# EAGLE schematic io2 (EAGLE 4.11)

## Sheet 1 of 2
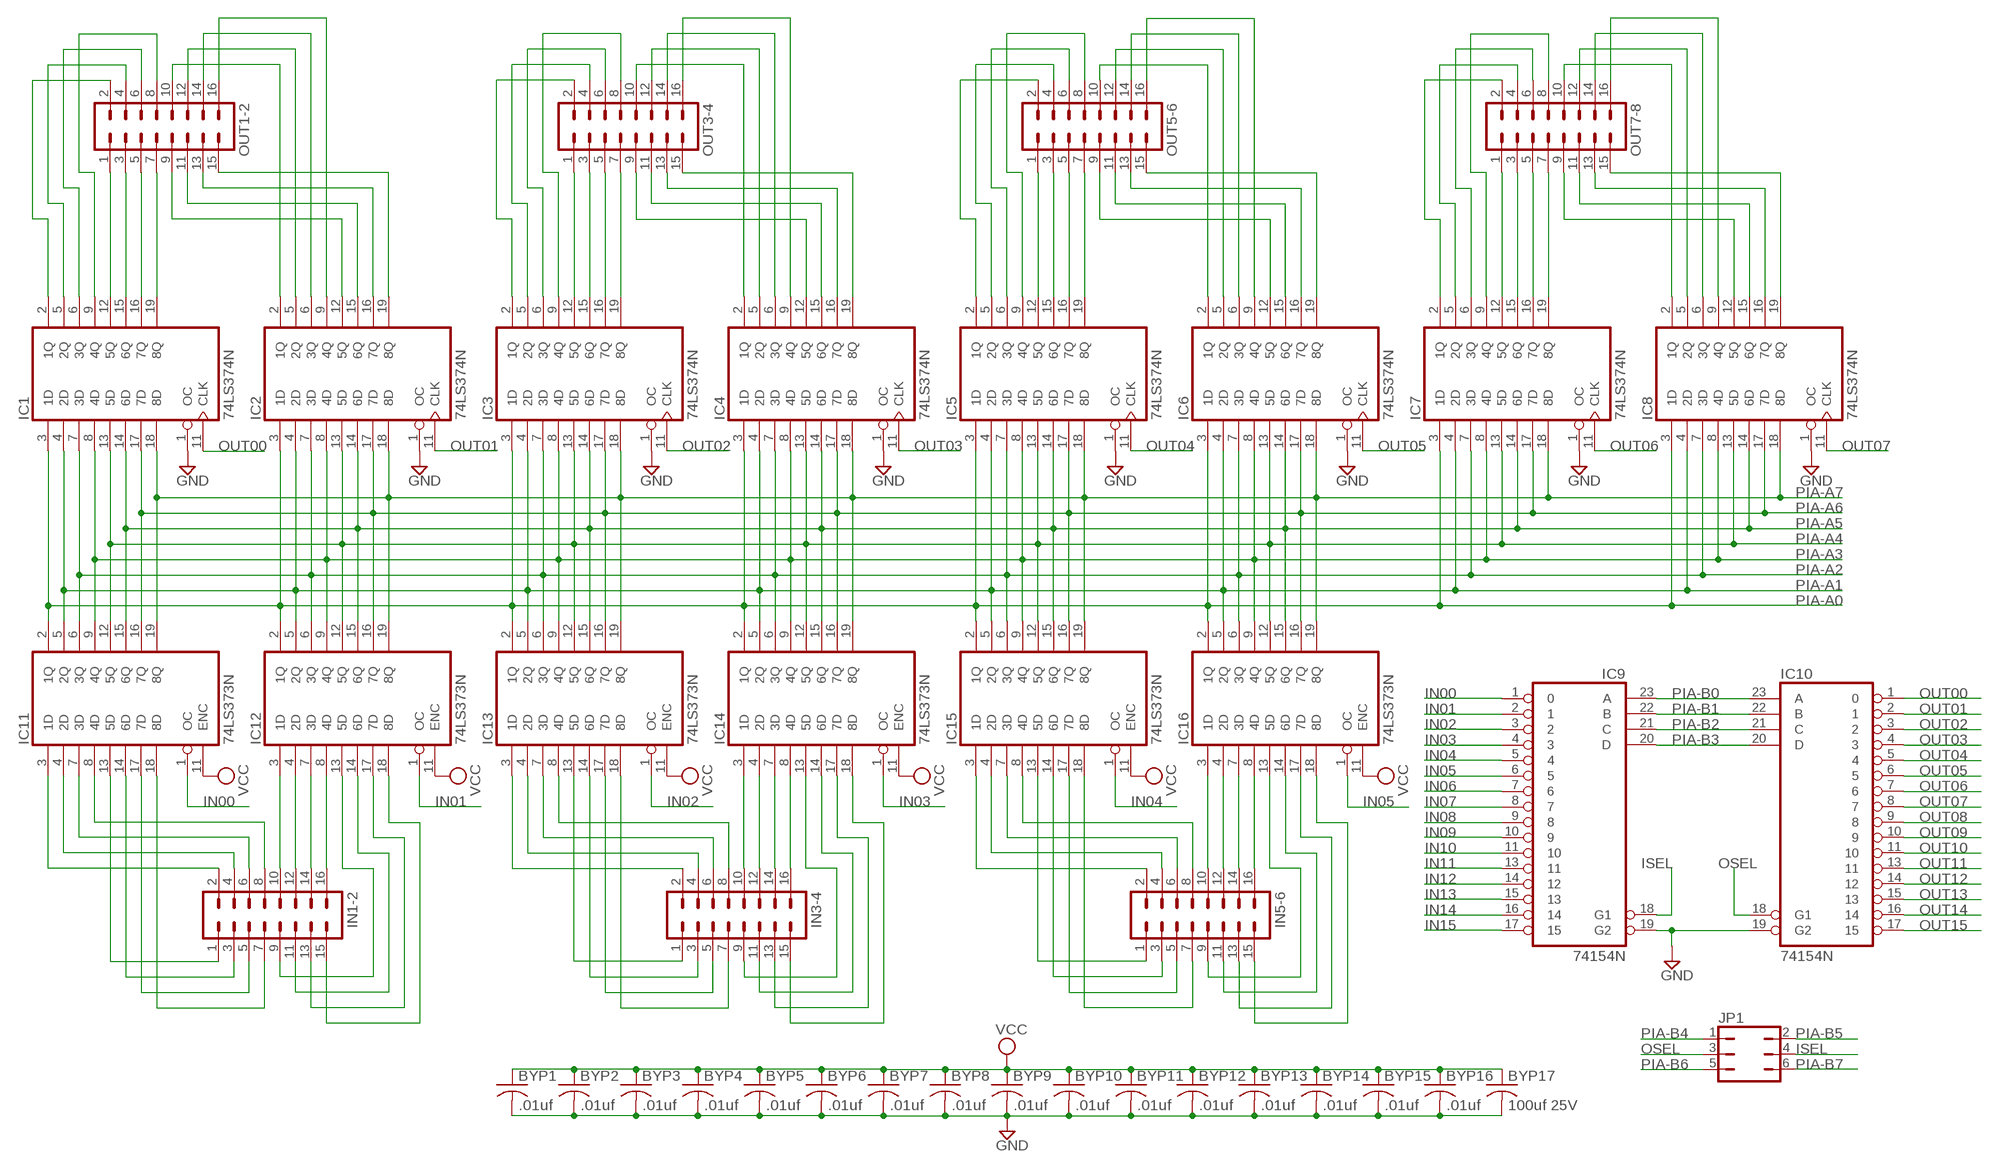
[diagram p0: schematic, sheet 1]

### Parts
BYP1  .01uf  C-US050-025X075  [C050-025X075]
BYP2  .01uf  C-US050-025X075  [C050-025X075]
BYP3  .01uf  C-US050-025X075  [C050-025X075]
BYP4  .01uf  C-US050-025X075  [C050-025X075]
BYP5  .01uf  C-US050-025X075  [C050-025X075]
BYP6  .01uf  C-US050-025X075  [C050-025X075]
BYP7  .01uf  C-US050-025X075  [C050-025X075]
BYP8  .01uf  C-US050-025X075  [C050-025X075]
BYP9  .01uf  C-US050-025X075  [C050-025X075]
BYP10  .01uf  C-US050-025X075  [C050-025X075]
BYP11  .01uf  C-US050-025X075  [C050-025X075]
BYP12  .01uf  C-US050-025X075  [C050-025X075]
BYP13  .01uf  C-US050-025X075  [C050-025X075]
BYP14  .01uf  C-US050-025X075  [C050-025X075]
BYP15  .01uf  C-US050-025X075  [C050-025X075]
BYP16  .01uf  C-US050-025X075  [C050-025X075]
BYP17  100uf 25V  C-US102-043X133  [C102-043X133]
IC1  74LS374N  [DIL20]
IC2  74LS374N  [DIL20]
IC3  74LS374N  [DIL20]
IC4  74LS374N  [DIL20]
IC5  74LS374N  [DIL20]
IC6  74LS374N  [DIL20]
IC7  74LS374N  [DIL20]
IC8  74LS374N  [DIL20]
IC9  74154N  [DIL24-6]
IC10  74154N  [DIL24-6]
IC11  74LS373N  [DIL20]
IC12  74LS373N  [DIL20]
IC13  74LS373N  [DIL20]
IC14  74LS373N  [DIL20]
IC15  74LS373N  [DIL20]
IC16  74LS373N  [DIL20]
IN1-2  MA08-2  [MA08-2]
IN3-4  MA08-2  [MA08-2]
IN5-6  MA08-2  [MA08-2]
JP1  JP3Q  [JP3Q]
OUT1-2  MA08-2  [MA08-2]
OUT3-4  MA08-2  [MA08-2]
OUT5-6  MA08-2  [MA08-2]
OUT7-8  MA08-2  [MA08-2]

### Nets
GND [Power]: BYP1.2 BYP2.2 BYP3.2 BYP4.2 BYP5.2 BYP6.2 BYP7.2 BYP8.2 BYP9.2 BYP10.2 BYP11.2 BYP12.2 BYP13.2 BYP14.2 BYP15.2 BYP16.2 BYP17.2 IC1.1(OC) IC2.1(OC) IC3.1(OC) IC4.1(OC) IC5.1(OC) IC6.1(OC) IC7.1(OC) IC8.1(OC) IC9.19(G2) IC10.19(G2) ; also sheet 2
IN00: IC9.1 IC11.1(OC)
IN01: IC9.2 IC12.1(OC)
IN02: IC9.3 IC13.1(OC)
IN03: IC9.4 IC14.1(OC)
IN04: IC9.5 IC15.1(OC)
IN05: IC9.6 IC16.1(OC)
IN06: IC9.7
IN07: IC9.8
IN08: IC9.9
IN09: IC9.10
IN10: IC9.11
IN11: IC9.13
IN12: IC9.14
IN13: IC9.15
IN14: IC9.16
IN15: IC9.17
ISEL: IC9.18(G1) JP1.4
N$1: IC12.3(1D) IN1-2.10
N$2: IC12.4(2D) IN1-2.12
N$7: IC12.7(3D) IN1-2.14
N$8: IC12.8(4D) IN1-2.16
N$9: IC11.8(4D) IN1-2.8
N$10: IC11.7(3D) IN1-2.6
N$11: IC11.4(2D) IN1-2.4
N$12: IC11.3(1D) IN1-2.2
N$13: IC11.13(5D) IN1-2.1
N$14: IC11.14(6D) IN1-2.3
N$15: IC11.17(7D) IN1-2.5
N$16: IC11.18(8D) IN1-2.7
N$17: IC12.13(5D) IN1-2.9
N$18: IC12.14(6D) IN1-2.11
N$19: IC12.17(7D) IN1-2.13
N$20: IC12.18(8D) IN1-2.15
N$26: IC5.2(1Q) IC7.2(1Q) OUT5-6.2 OUT7-8.2
N$29: IC14.3(1D) IN3-4.10
N$30: IC14.4(2D) IN3-4.12
N$31: IC14.7(3D) IN3-4.14
N$32: IC14.8(4D) IN3-4.16
N$33: IC3.12(5Q) OUT3-4.1
N$34: IC3.15(6Q) OUT3-4.3
N$35: IC3.16(7Q) OUT3-4.5
N$36: IC3.19(8Q) OUT3-4.7
N$37: IC13.3(1D) IN3-4.2
N$38: IC13.4(2D) IN3-4.4
N$39: IC13.7(3D) IN3-4.6
N$40: IC13.8(4D) IN3-4.8
N$41: IC14.13(5D) IN3-4.9
N$42: IC14.14(6D) IN3-4.11
N$43: IC14.17(7D) IN3-4.13
N$44: IC14.18(8D) IN3-4.15
N$45: IC13.13(5D) IN3-4.1
N$46: IC13.14(6D) IN3-4.3
N$47: IC13.17(7D) IN3-4.5
N$48: IC13.18(8D) IN3-4.7
N$49: IC3.5(2Q) OUT3-4.4
N$50: IC3.6(3Q) OUT3-4.6
N$51: IC3.2(1Q) OUT3-4.2
N$52: IC3.9(4Q) OUT3-4.8
N$53: IC1.12(5Q) OUT1-2.1
N$54: IC1.15(6Q) OUT1-2.3
N$55: IC1.16(7Q) OUT1-2.5
N$56: IC1.19(8Q) OUT1-2.7
N$57: IC1.2(1Q) OUT1-2.2
N$58: IC1.5(2Q) OUT1-2.4
N$59: IC1.6(3Q) OUT1-2.6
N$60: IC1.9(4Q) OUT1-2.8
N$61: IC2.19(8Q) OUT1-2.15
N$62: IC2.16(7Q) OUT1-2.13
N$63: IC2.15(6Q) OUT1-2.11
N$64: IC2.12(5Q) OUT1-2.9
N$65: IC2.2(1Q) OUT1-2.10
N$66: IC2.5(2Q) OUT1-2.12
N$67: IC2.6(3Q) OUT1-2.14
N$68: IC2.9(4Q) OUT1-2.16
N$69: IC4.2(1Q) OUT3-4.10
N$70: IC4.5(2Q) OUT3-4.12
N$71: IC4.6(3Q) OUT3-4.14
N$72: IC4.9(4Q) OUT3-4.16
N$73: IC4.19(8Q) OUT3-4.15
N$74: IC4.16(7Q) OUT3-4.13
N$75: IC4.15(6Q) OUT3-4.11
N$76: IC4.12(5Q) OUT3-4.9
N$77: IC16.3(1D) IN5-6.10
N$78: IC16.4(2D) IN5-6.12
N$79: IC16.7(3D) IN5-6.14
N$80: IC16.8(4D) IN5-6.16
N$81: IC5.12(5Q) OUT5-6.1
N$82: IC5.15(6Q) OUT5-6.3
N$83: IC5.16(7Q) OUT5-6.5
N$84: IC5.19(8Q) OUT5-6.7
N$85: IC7.12(5Q) OUT7-8.1
N$86: IC7.15(6Q) OUT7-8.3
N$87: IC7.16(7Q) OUT7-8.5
N$88: IC7.19(8Q) OUT7-8.7
N$89: IC5.5(2Q) OUT5-6.4
N$90: IC5.6(3Q) OUT5-6.6
N$91: IC5.9(4Q) OUT5-6.8
N$92: IC6.12(5Q) OUT5-6.9
N$93: IC6.15(6Q) OUT5-6.11
N$95: IC6.16(7Q) OUT5-6.13
N$96: IC6.19(8Q) OUT5-6.15
N$97: IC6.2(1Q) OUT5-6.10
N$98: IC6.5(2Q) OUT5-6.12
N$99: IC6.6(3Q) OUT5-6.14
N$100: IC6.9(4Q) OUT5-6.16
N$101: IC15.3(1D) IN5-6.2
N$102: IC15.4(2D) IN5-6.4
N$103: IC15.7(3D) IN5-6.6
N$104: IC15.8(4D) IN5-6.8
N$105: IC16.13(5D) IN5-6.9
N$106: IC16.14(6D) IN5-6.11
N$107: IC16.17(7D) IN5-6.13
N$108: IC16.18(8D) IN5-6.15
N$109: IC15.13(5D) IN5-6.1
N$110: IC15.14(6D) IN5-6.3
N$111: IC15.17(7D) IN5-6.5
N$112: IC15.18(8D) IN5-6.7
N$113: IC8.19(8Q) OUT7-8.15
N$114: IC8.16(7Q) OUT7-8.13
N$115: IC8.15(6Q) OUT7-8.11
N$116: IC8.12(5Q) OUT7-8.9
N$117: IC8.2(1Q) OUT7-8.10
N$118: IC8.5(2Q) OUT7-8.12
N$119: IC8.6(3Q) OUT7-8.14
N$120: IC8.9(4Q) OUT7-8.16
N$121: IC7.9(4Q) OUT7-8.8
N$122: IC7.6(3Q) OUT7-8.6
N$123: IC7.5(2Q) OUT7-8.4
OSEL: IC10.18(G1) JP1.3
OUT00: IC1.11(CLK) IC10.1
OUT01: IC2.11(CLK) IC10.2
OUT02: IC3.11(CLK) IC10.3
OUT03: IC4.11(CLK) IC10.4
OUT04: IC5.11(CLK) IC10.5
OUT05: IC6.11(CLK) IC10.6
OUT06: IC7.11(CLK) IC10.7
OUT07: IC8.11(CLK) IC10.8
OUT08: IC10.9
OUT09: IC10.10
OUT10: IC10.11
OUT11: IC10.13
OUT12: IC10.14
OUT13: IC10.15
OUT14: IC10.16
OUT15: IC10.17
PIA-A0: IC1.3(1D) IC2.3(1D) IC3.3(1D) IC4.3(1D) IC5.3(1D) IC6.3(1D) IC7.3(1D) IC8.3(1D) IC11.2(1Q) IC12.2(1Q) IC13.2(1Q) IC14.2(1Q) IC15.2(1Q) IC16.2(1Q) ; also sheet 2
PIA-A1: IC1.4(2D) IC2.4(2D) IC3.4(2D) IC4.4(2D) IC5.4(2D) IC6.4(2D) IC7.4(2D) IC8.4(2D) IC11.5(2Q) IC12.5(2Q) IC13.5(2Q) IC14.5(2Q) IC15.5(2Q) IC16.5(2Q) ; also sheet 2
PIA-A2: IC1.7(3D) IC2.7(3D) IC3.7(3D) IC4.7(3D) IC5.7(3D) IC6.7(3D) IC7.7(3D) IC8.7(3D) IC11.6(3Q) IC12.6(3Q) IC13.6(3Q) IC14.6(3Q) IC15.6(3Q) IC16.6(3Q) ; also sheet 2
PIA-A3: IC1.8(4D) IC2.8(4D) IC3.8(4D) IC4.8(4D) IC5.8(4D) IC6.8(4D) IC7.8(4D) IC8.8(4D) IC11.9(4Q) IC12.9(4Q) IC13.9(4Q) IC14.9(4Q) IC15.9(4Q) IC16.9(4Q) ; also sheet 2
PIA-A4: IC1.13(5D) IC2.13(5D) IC3.13(5D) IC4.13(5D) IC5.13(5D) IC6.13(5D) IC7.13(5D) IC8.13(5D) IC11.12(5Q) IC12.12(5Q) IC13.12(5Q) IC14.12(5Q) IC15.12(5Q) IC16.12(5Q) ; also sheet 2
PIA-A5: IC1.14(6D) IC2.14(6D) IC3.14(6D) IC4.14(6D) IC5.14(6D) IC6.14(6D) IC7.14(6D) IC8.14(6D) IC11.15(6Q) IC12.15(6Q) IC13.15(6Q) IC14.15(6Q) IC15.15(6Q) IC16.15(6Q) ; also sheet 2
PIA-A6: IC1.17(7D) IC2.17(7D) IC3.17(7D) IC4.17(7D) IC5.17(7D) IC6.17(7D) IC7.17(7D) IC8.17(7D) IC11.16(7Q) IC12.16(7Q) IC13.16(7Q) IC14.16(7Q) IC15.16(7Q) IC16.16(7Q) ; also sheet 2
PIA-A7: IC1.18(8D) IC2.18(8D) IC3.18(8D) IC4.18(8D) IC5.18(8D) IC6.18(8D) IC7.18(8D) IC8.18(8D) IC11.19(8Q) IC12.19(8Q) IC13.19(8Q) IC14.19(8Q) IC15.19(8Q) IC16.19(8Q) ; also sheet 2
PIA-B0: IC9.23(A) IC10.23(A) ; also sheet 2
PIA-B1: IC9.22(B) IC10.22(B) ; also sheet 2
PIA-B2: IC9.21(C) IC10.21(C) ; also sheet 2
PIA-B3: IC9.20(D) IC10.20(D) ; also sheet 2
PIA-B4: JP1.1 ; also sheet 2
PIA-B5: JP1.2 ; also sheet 2
PIA-B6: JP1.5 ; also sheet 2
PIA-B7: JP1.6 ; also sheet 2
VCC [Power]: BYP1.1 BYP2.1 BYP3.1 BYP4.1 BYP5.1 BYP6.1 BYP7.1 BYP8.1 BYP9.1 BYP10.1 BYP11.1 BYP12.1 BYP13.1 BYP14.1 BYP15.1 BYP16.1 BYP17.1 IC11.11(ENC) IC12.11(ENC) IC13.11(ENC) IC14.11(ENC) IC15.11(ENC) IC16.11(ENC) ; also sheet 2

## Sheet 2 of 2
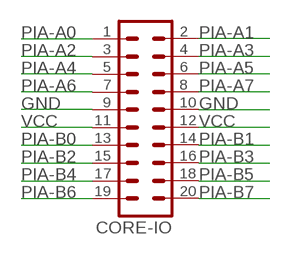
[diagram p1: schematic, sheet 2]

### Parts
CORE-IO  MA10-2  [MA10-2]

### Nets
GND [Power]: CORE-IO.9 CORE-IO.10 ; also sheet 1
PIA-A0: CORE-IO.1 ; also sheet 1
PIA-A1: CORE-IO.2 ; also sheet 1
PIA-A2: CORE-IO.3 ; also sheet 1
PIA-A3: CORE-IO.4 ; also sheet 1
PIA-A4: CORE-IO.5 ; also sheet 1
PIA-A5: CORE-IO.6 ; also sheet 1
PIA-A6: CORE-IO.7 ; also sheet 1
PIA-A7: CORE-IO.8 ; also sheet 1
PIA-B0: CORE-IO.13 ; also sheet 1
PIA-B1: CORE-IO.14 ; also sheet 1
PIA-B2: CORE-IO.15 ; also sheet 1
PIA-B3: CORE-IO.16 ; also sheet 1
PIA-B4: CORE-IO.17 ; also sheet 1
PIA-B5: CORE-IO.18 ; also sheet 1
PIA-B6: CORE-IO.19 ; also sheet 1
PIA-B7: CORE-IO.20 ; also sheet 1
VCC [Power]: CORE-IO.11 CORE-IO.12 ; also sheet 1

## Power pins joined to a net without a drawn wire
GND: IC1.10(GND) IC2.10(GND) IC3.10(GND) IC4.10(GND) IC5.10(GND) IC6.10(GND) IC7.10(GND) IC8.10(GND) IC9.12(GND) IC10.12(GND) IC11.10(GND) IC12.10(GND) IC13.10(GND) IC14.10(GND) IC15.10(GND) IC16.10(GND)
VCC: IC1.20(VCC) IC2.20(VCC) IC3.20(VCC) IC4.20(VCC) IC5.20(VCC) IC6.20(VCC) IC7.20(VCC) IC8.20(VCC) IC9.24(VCC) IC10.24(VCC) IC11.20(VCC) IC12.20(VCC) IC13.20(VCC) IC14.20(VCC) IC15.20(VCC) IC16.20(VCC)

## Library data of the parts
BYP1-BYP17 = rcl:C-US: CAPACITOR, American symbol
CORE-IO = con-lstb:MA10-2: PIN HEADER
IC1-IC8 = 74xx-us:74*374: Octal D type transparent LATCH, edge triggered
IC9 IC10 = 74xx-us:74*154: 4-line to 16-line data SELECTOR/MULTIPLEXER
IC11-IC16 = 74xx-us:74*373: Octal D type transparent LATCH, edge triggered
IN1-2 IN3-4 IN5-6 OUT1-2 OUT3-4 OUT5-6 OUT7-8 = con-lstb:MA08-2: PIN HEADER
JP1 = jumper:JP3Q: JUMPER

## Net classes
1 Power: width 0.508 mm, drill 0.254 mm, clearance 0.254 mm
